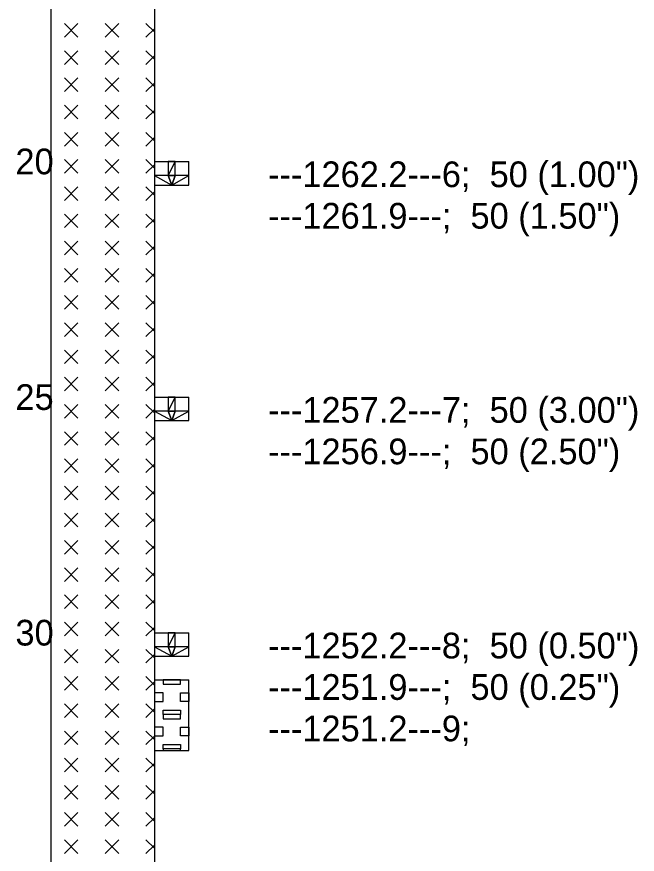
# Model space of a CAD drawing. Extents: x 2150161.5 to 2150203.1, y 143779.5 to 143868.5.
# Drawn here: x 2150176.192 to 2150179.186, y 143821.223 to 143825.262 of the extents above; entities that cross this region are included whole.
import ezdxf

# ---------------------------------------------------------------- set-up
doc = ezdxf.new("R2010")
doc.units = 0
doc.layers.add('Default', color=7, linetype='Continuous')

msp = doc.modelspace()

# ---------------------------------------------------------------- linework, layer by layer
at = {"layer": 'Default'}
for points in [[(2150176.3564, 143829.1095), (2150176.3564, 143816.9504)], [(2150176.8564, 143829.1095), (2150176.8564, 143816.9504)], [(2150176.4876, 143825.2292), (2150176.422, 143825.1636)], [(2150176.422, 143825.2292), (2150176.4876, 143825.1636)], [(2150176.6844, 143825.2292), (2150176.6188, 143825.1636)], [(2150176.6188, 143825.2292), (2150176.6844, 143825.1636)], [(2150176.8157, 143825.2292), (2150176.8564, 143825.1885)], [(2150176.8564, 143825.2042), (2150176.8157, 143825.1636)], [(2150176.4876, 143825.0979), (2150176.422, 143825.0323)], [(2150176.422, 143825.0979), (2150176.4876, 143825.0323)], [(2150176.6844, 143825.0979), (2150176.6188, 143825.0323)], [(2150176.6188, 143825.0979), (2150176.6844, 143825.0323)], [(2150176.8157, 143825.0979), (2150176.8564, 143825.0573)], [(2150176.8564, 143825.073), (2150176.8157, 143825.0323)], [(2150176.4876, 143824.9667), (2150176.422, 143824.9011)], [(2150176.422, 143824.9667), (2150176.4876, 143824.9011)], [(2150176.6844, 143824.9667), (2150176.6188, 143824.9011)], [(2150176.6188, 143824.9667), (2150176.6844, 143824.9011)], [(2150176.8157, 143824.9667), (2150176.8564, 143824.926)], [(2150176.8564, 143824.9418), (2150176.8157, 143824.9011)], [(2150176.4876, 143824.8355), (2150176.422, 143824.7699)], [(2150176.422, 143824.8355), (2150176.4876, 143824.7699)], [(2150176.6844, 143824.8355), (2150176.6188, 143824.7699)], [(2150176.6188, 143824.8355), (2150176.6844, 143824.7699)], [(2150176.8157, 143824.8355), (2150176.8564, 143824.7948)], [(2150176.8564, 143824.8105), (2150176.8157, 143824.7699)], [(2150176.4876, 143824.7042), (2150176.422, 143824.6386)], [(2150176.422, 143824.7042), (2150176.4876, 143824.6386)], [(2150176.6844, 143824.7042), (2150176.6188, 143824.6386)], [(2150176.6188, 143824.7042), (2150176.6844, 143824.6386)], [(2150176.8157, 143824.7042), (2150176.8564, 143824.6636)], [(2150176.8564, 143824.6793), (2150176.8157, 143824.6386)], [(2150176.4876, 143824.573), (2150176.422, 143824.5074)], [(2150176.422, 143824.573), (2150176.4876, 143824.5074)], [(2150176.6844, 143824.573), (2150176.6188, 143824.5074)], [(2150176.6188, 143824.573), (2150176.6844, 143824.5074)], [(2150176.8157, 143824.573), (2150176.8564, 143824.5323)], [(2150176.8564, 143824.5641), (2150177.023, 143824.5641)], [(2150177.023, 143824.4504), (2150177.023, 143824.5641)], [(2150176.8564, 143824.5481), (2150176.8157, 143824.5074)], [(2150176.4876, 143824.4418), (2150176.422, 143824.3762)], [(2150176.422, 143824.4418), (2150176.4876, 143824.3762)], [(2150176.6844, 143824.4418), (2150176.6188, 143824.3762)], [(2150176.6188, 143824.4418), (2150176.6844, 143824.3762)], [(2150176.8157, 143824.4418), (2150176.8564, 143824.4011)], [(2150176.8564, 143824.4504), (2150177.023, 143824.4504)], [(2150176.8564, 143824.4168), (2150176.8157, 143824.3762)], [(2150176.4876, 143824.3105), (2150176.422, 143824.2449)], [(2150176.422, 143824.3105), (2150176.4876, 143824.2449)], [(2150176.6844, 143824.3105), (2150176.6188, 143824.2449)], [(2150176.6188, 143824.3105), (2150176.6844, 143824.2449)], [(2150176.8157, 143824.3105), (2150176.8564, 143824.2699)], [(2150176.8564, 143824.2856), (2150176.8157, 143824.2449)], [(2150176.4876, 143824.1793), (2150176.422, 143824.1137)], [(2150176.422, 143824.1793), (2150176.4876, 143824.1137)], [(2150176.6844, 143824.1793), (2150176.6188, 143824.1137)], [(2150176.6188, 143824.1793), (2150176.6844, 143824.1137)], [(2150176.8157, 143824.1793), (2150176.8564, 143824.1386)], [(2150176.8564, 143824.1544), (2150176.8157, 143824.1137)], [(2150176.4876, 143824.0481), (2150176.422, 143823.9825)], [(2150176.422, 143824.0481), (2150176.4876, 143823.9825)], [(2150176.6844, 143824.0481), (2150176.6188, 143823.9825)], [(2150176.6188, 143824.0481), (2150176.6844, 143823.9825)], [(2150176.8157, 143824.0481), (2150176.8564, 143824.0074)], [(2150176.8564, 143824.0231), (2150176.8157, 143823.9825)], [(2150176.4876, 143823.9168), (2150176.422, 143823.8512)], [(2150176.422, 143823.9168), (2150176.4876, 143823.8512)], [(2150176.6844, 143823.9168), (2150176.6188, 143823.8512)], [(2150176.6188, 143823.9168), (2150176.6844, 143823.8512)], [(2150176.8157, 143823.9168), (2150176.8564, 143823.8762)], [(2150176.8564, 143823.8919), (2150176.8157, 143823.8512)], [(2150176.4876, 143823.7856), (2150176.422, 143823.72)], [(2150176.422, 143823.7856), (2150176.4876, 143823.72)], [(2150176.6844, 143823.7856), (2150176.6188, 143823.72)], [(2150176.6188, 143823.7856), (2150176.6844, 143823.72)], [(2150176.8157, 143823.7856), (2150176.8564, 143823.7449)], [(2150176.8564, 143823.7607), (2150176.8157, 143823.72)], [(2150176.4876, 143823.6544), (2150176.422, 143823.5888)], [(2150176.422, 143823.6544), (2150176.4876, 143823.5888)], [(2150176.6844, 143823.6544), (2150176.6188, 143823.5888)], [(2150176.6188, 143823.6544), (2150176.6844, 143823.5888)], [(2150176.8157, 143823.6544), (2150176.8564, 143823.6137)], [(2150176.8564, 143823.6294), (2150176.8157, 143823.5888)], [(2150176.4876, 143823.5231), (2150176.422, 143823.4575)], [(2150176.422, 143823.5231), (2150176.4876, 143823.4575)], [(2150176.6844, 143823.5231), (2150176.6188, 143823.4575)], [(2150176.6188, 143823.5231), (2150176.6844, 143823.4575)], [(2150176.8157, 143823.5231), (2150176.8564, 143823.4825)], [(2150176.8564, 143823.4982), (2150176.8157, 143823.4575)], [(2150176.4876, 143823.3919), (2150176.422, 143823.3263)], [(2150176.422, 143823.3919), (2150176.4876, 143823.3263)], [(2150176.6844, 143823.3919), (2150176.6188, 143823.3263)], [(2150176.6188, 143823.3919), (2150176.6844, 143823.3263)], [(2150176.8157, 143823.3919), (2150176.8564, 143823.3512)], [(2150176.8564, 143823.4277), (2150177.023, 143823.4277)], [(2150177.023, 143823.3141), (2150177.023, 143823.4277)], [(2150176.8564, 143823.367), (2150176.8157, 143823.3263)], [(2150176.8564, 143823.3141), (2150177.023, 143823.3141)], [(2150176.4876, 143823.2607), (2150176.422, 143823.1951)], [(2150176.422, 143823.2607), (2150176.4876, 143823.1951)], [(2150176.6844, 143823.2607), (2150176.6188, 143823.1951)], [(2150176.6188, 143823.2607), (2150176.6844, 143823.1951)], [(2150176.8157, 143823.2607), (2150176.8564, 143823.22)], [(2150176.8564, 143823.2357), (2150176.8157, 143823.1951)], [(2150176.4876, 143823.1294), (2150176.422, 143823.0638)], [(2150176.422, 143823.1294), (2150176.4876, 143823.0638)], [(2150176.6844, 143823.1294), (2150176.6188, 143823.0638)], [(2150176.6188, 143823.1294), (2150176.6844, 143823.0638)], [(2150176.8157, 143823.1294), (2150176.8564, 143823.0888)], [(2150176.8564, 143823.1045), (2150176.8157, 143823.0638)], [(2150176.4876, 143822.9982), (2150176.422, 143822.9326)], [(2150176.422, 143822.9982), (2150176.4876, 143822.9326)], [(2150176.6844, 143822.9982), (2150176.6188, 143822.9326)], [(2150176.6188, 143822.9982), (2150176.6844, 143822.9326)], [(2150176.8157, 143822.9982), (2150176.8564, 143822.9575)], [(2150176.8564, 143822.9733), (2150176.8157, 143822.9326)], [(2150176.4876, 143822.867), (2150176.422, 143822.8014)], [(2150176.422, 143822.867), (2150176.4876, 143822.8014)], [(2150176.6844, 143822.867), (2150176.6188, 143822.8014)], [(2150176.6188, 143822.867), (2150176.6844, 143822.8014)], [(2150176.8157, 143822.867), (2150176.8564, 143822.8263)], [(2150176.8564, 143822.842), (2150176.8157, 143822.8014)], [(2150176.4876, 143822.7357), (2150176.422, 143822.6701)], [(2150176.422, 143822.7357), (2150176.4876, 143822.6701)], [(2150176.6844, 143822.7357), (2150176.6188, 143822.6701)], [(2150176.6188, 143822.7357), (2150176.6844, 143822.6701)], [(2150176.8157, 143822.7357), (2150176.8564, 143822.6951)], [(2150176.8564, 143822.7108), (2150176.8157, 143822.6701)], [(2150176.4876, 143822.6045), (2150176.422, 143822.5389)], [(2150176.422, 143822.6045), (2150176.4876, 143822.5389)], [(2150176.6844, 143822.6045), (2150176.6188, 143822.5389)], [(2150176.6188, 143822.6045), (2150176.6844, 143822.5389)], [(2150176.8157, 143822.6045), (2150176.8564, 143822.5638)], [(2150176.8564, 143822.5796), (2150176.8157, 143822.5389)], [(2150176.4876, 143822.4733), (2150176.422, 143822.4077)], [(2150176.422, 143822.4733), (2150176.4876, 143822.4077)], [(2150176.6844, 143822.4733), (2150176.6188, 143822.4077)], [(2150176.6188, 143822.4733), (2150176.6844, 143822.4077)], [(2150176.8157, 143822.4733), (2150176.8564, 143822.4326)], [(2150176.8564, 143822.4483), (2150176.8157, 143822.4077)], [(2150176.4876, 143822.342), (2150176.422, 143822.2764)], [(2150176.422, 143822.342), (2150176.4876, 143822.2764)], [(2150176.6844, 143822.342), (2150176.6188, 143822.2764)], [(2150176.6188, 143822.342), (2150176.6844, 143822.2764)], [(2150176.8157, 143822.342), (2150176.8564, 143822.3014)], [(2150176.8564, 143822.3171), (2150176.8157, 143822.2764)], [(2150176.8564, 143822.2913), (2150177.023, 143822.2913)], [(2150177.023, 143822.1777), (2150177.023, 143822.2913)], [(2150176.4876, 143822.2108), (2150176.422, 143822.1452)], [(2150176.422, 143822.2108), (2150176.4876, 143822.1452)], [(2150176.6844, 143822.2108), (2150176.6188, 143822.1452)], [(2150176.6188, 143822.2108), (2150176.6844, 143822.1452)], [(2150176.8157, 143822.2108), (2150176.8564, 143822.1701)], [(2150176.8564, 143822.1859), (2150176.8157, 143822.1452)], [(2150176.8564, 143822.1777), (2150177.023, 143822.1777)], [(2150176.4876, 143822.0796), (2150176.422, 143822.014)], [(2150176.422, 143822.0796), (2150176.4876, 143822.014)], [(2150176.6844, 143822.0796), (2150176.6188, 143822.014)], [(2150176.6188, 143822.0796), (2150176.6844, 143822.014)], [(2150176.8157, 143822.0796), (2150176.8564, 143822.0389)], [(2150176.8564, 143822.0641), (2150177.023, 143822.0641)], [(2150177.023, 143821.7232), (2150177.023, 143822.0641)], [(2150176.8564, 143822.0546), (2150176.8157, 143822.014)], [(2150176.4876, 143821.9483), (2150176.422, 143821.8827)], [(2150176.422, 143821.9483), (2150176.4876, 143821.8827)], [(2150176.6844, 143821.9483), (2150176.6188, 143821.8827)], [(2150176.6188, 143821.9483), (2150176.6844, 143821.8827)], [(2150176.8157, 143821.9483), (2150176.8564, 143821.9077)], [(2150176.8564, 143821.9234), (2150176.8157, 143821.8827)], [(2150176.4876, 143821.8171), (2150176.422, 143821.7515)], [(2150176.422, 143821.8171), (2150176.4876, 143821.7515)], [(2150176.6844, 143821.8171), (2150176.6188, 143821.7515)], [(2150176.6188, 143821.8171), (2150176.6844, 143821.7515)], [(2150176.8157, 143821.8171), (2150176.8564, 143821.7764)], [(2150176.8564, 143821.7922), (2150176.8157, 143821.7515)], [(2150176.8564, 143821.7232), (2150177.023, 143821.7232)], [(2150176.4876, 143821.6859), (2150176.422, 143821.6203)], [(2150176.422, 143821.6859), (2150176.4876, 143821.6203)], [(2150176.6844, 143821.6859), (2150176.6188, 143821.6203)], [(2150176.6188, 143821.6859), (2150176.6844, 143821.6203)], [(2150176.8157, 143821.6859), (2150176.8564, 143821.6452)], [(2150176.8564, 143821.6609), (2150176.8157, 143821.6203)], [(2150176.4876, 143821.5546), (2150176.422, 143821.489)], [(2150176.422, 143821.5546), (2150176.4876, 143821.489)], [(2150176.6844, 143821.5546), (2150176.6188, 143821.489)], [(2150176.6188, 143821.5546), (2150176.6844, 143821.489)], [(2150176.8157, 143821.5546), (2150176.8564, 143821.514)], [(2150176.8564, 143821.5297), (2150176.8157, 143821.489)], [(2150176.4876, 143821.4234), (2150176.422, 143821.3578)], [(2150176.422, 143821.4234), (2150176.4876, 143821.3578)], [(2150176.6844, 143821.4234), (2150176.6188, 143821.3578)], [(2150176.6188, 143821.4234), (2150176.6844, 143821.3578)], [(2150176.8157, 143821.4234), (2150176.8564, 143821.3827)], [(2150176.8564, 143821.3985), (2150176.8157, 143821.3578)], [(2150176.4876, 143821.2922), (2150176.422, 143821.2266)], [(2150176.422, 143821.2922), (2150176.4876, 143821.2266)], [(2150176.6844, 143821.2922), (2150176.6188, 143821.2266)], [(2150176.6188, 143821.2922), (2150176.6844, 143821.2266)], [(2150176.8157, 143821.2922), (2150176.8564, 143821.2515)], [(2150176.8564, 143821.2672), (2150176.8157, 143821.2266)]]:
    msp.add_lwpolyline(points, dxfattribs=at)
for points in [[(2150176.923, 143824.4959), (2150176.9564, 143824.4959), (2150176.9564, 143824.5641), (2150176.923, 143824.4959)], [(2150176.923, 143824.4959), (2150176.9564, 143824.5641), (2150176.923, 143824.5641), (2150176.923, 143824.4959)], [(2150176.923, 143824.4959), (2150176.8564, 143824.4959), (2150176.9397, 143824.4504), (2150176.923, 143824.4959)], [(2150176.923, 143824.4959), (2150176.9397, 143824.4504), (2150176.9564, 143824.4959), (2150176.923, 143824.4959)], [(2150176.9397, 143824.4504), (2150177.023, 143824.4959), (2150176.9564, 143824.4959), (2150176.9397, 143824.4504)], [(2150176.923, 143823.3595), (2150176.9564, 143823.3595), (2150176.9564, 143823.4277), (2150176.923, 143823.3595)], [(2150176.923, 143823.3595), (2150176.9564, 143823.4277), (2150176.923, 143823.4277), (2150176.923, 143823.3595)], [(2150176.923, 143823.3595), (2150176.8564, 143823.3595), (2150176.9397, 143823.3141), (2150176.923, 143823.3595)], [(2150176.923, 143823.3595), (2150176.9397, 143823.3141), (2150176.9564, 143823.3595), (2150176.923, 143823.3595)], [(2150176.9397, 143823.3141), (2150177.023, 143823.3595), (2150176.9564, 143823.3595), (2150176.9397, 143823.3141)], [(2150176.923, 143822.2232), (2150176.9564, 143822.2232), (2150176.9564, 143822.2913), (2150176.923, 143822.2232)], [(2150176.923, 143822.2232), (2150176.9564, 143822.2913), (2150176.923, 143822.2913), (2150176.923, 143822.2232)], [(2150176.923, 143822.2232), (2150176.8564, 143822.2232), (2150176.9397, 143822.1777), (2150176.923, 143822.2232)], [(2150176.923, 143822.2232), (2150176.9397, 143822.1777), (2150176.9564, 143822.2232), (2150176.923, 143822.2232)], [(2150176.9397, 143822.1777), (2150177.023, 143822.2232), (2150176.9564, 143822.2232), (2150176.9397, 143822.1777)], [(2150176.898, 143822.0641), (2150176.898, 143822.0432), (2150176.9814, 143822.0432), (2150176.9814, 143822.0641)], [(2150176.8564, 143821.9599), (2150176.898, 143821.9599), (2150176.898, 143822.0016), (2150176.8564, 143822.0016)], [(2150177.023, 143821.9599), (2150176.9814, 143821.9599), (2150176.9814, 143822.0016), (2150177.023, 143822.0016)], [(2150176.898, 143821.8974), (2150176.898, 143821.9182), (2150176.9814, 143821.9182), (2150176.9814, 143821.8974)], [(2150176.898, 143821.8974), (2150176.898, 143821.8766), (2150176.9814, 143821.8766), (2150176.9814, 143821.8974)], [(2150176.8564, 143821.7932), (2150176.898, 143821.7932), (2150176.898, 143821.8349), (2150176.8564, 143821.8349)], [(2150177.023, 143821.7932), (2150176.9814, 143821.7932), (2150176.9814, 143821.8349), (2150177.023, 143821.8349)], [(2150176.898, 143821.7307), (2150176.898, 143821.7516), (2150176.9814, 143821.7516), (2150176.9814, 143821.7307)], [(2150176.9814, 143821.7307), (2150176.898, 143821.7307), (2150176.898, 143821.7232), (2150176.9814, 143821.7232)]]:
    msp.add_lwpolyline(points, close=True, dxfattribs=at)

# ---------------------------------------------------------------- texts
for s, p in [('20', (2150176.1859, 143824.5021)), ('---1262.2---6;  50 (1.00")', (2150177.4044, 143824.4401)), ('---1261.9---;  50 (1.50")', (2150177.4044, 143824.2401)), ('25', (2150176.1859, 143823.3657)), ('---1257.2---7;  50 (3.00")', (2150177.4044, 143823.3037)), ('---1256.9---;  50 (2.50")', (2150177.4044, 143823.1037)), ('30', (2150176.1859, 143822.2293)), ('---1252.2---8;  50 (0.50")', (2150177.4044, 143822.1673)), ('---1251.9---;  50 (0.25")', (2150177.4044, 143821.9673)), ('---1251.2---9;', (2150177.4044, 143821.7673))]:
    msp.add_text(s, height=0.124, dxfattribs=at).set_placement(p)

doc.saveas('drawing.dxf')
